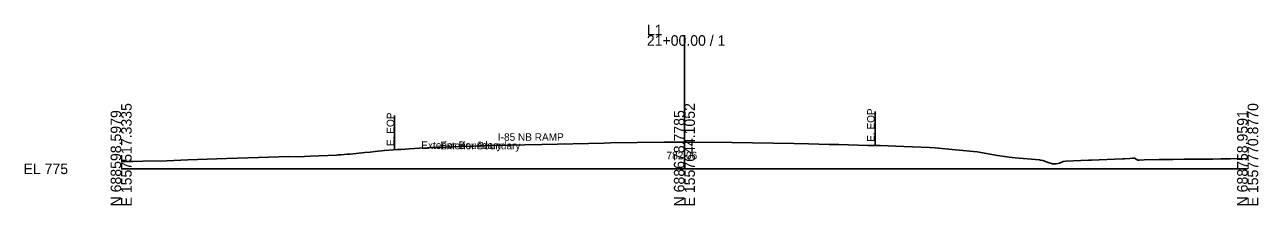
# Model space of a CAD drawing. Extents: x -26 to 2603, y -3010 to 9589.
# Drawn here: x -25.7 to 302.8, y 4490.3 to 4538.3 of the extents above; entities that cross this region are included whole.
import ezdxf

# ---------------------------------------------------------------- set-up
doc = ezdxf.new("R2010")
doc.units = 0
for name, color, linetype in [('Default', 7, 'Continuous'), ('Exist Cross Section Cell', 7, 'Continuous'), ('Exist XS Center Line Elevation Label', 7, 'Continuous'), ('Exist XS Ground Line', 7, 'Continuous'), ('Prop XS Label Text', 7, 'Continuous'), ('Prop XS Side Slope Text', 7, 'Continuous')]:
    doc.layers.add(name, color=color, linetype=linetype)

msp = doc.modelspace()

# ---------------------------------------------------------------- linework, layer by layer
at = {"layer": 'Exist Cross Section Cell'}
for p, q in [((150, 4500), (150, 4535.54)), ((0, 4500), (150, 4500)), ((150, 4500), (300, 4500))]:
    msp.add_line(p, q, dxfattribs=at)
at = {"layer": 'Exist XS Ground Line'}
msp.add_lwpolyline([(0, 4501.92), (3.11, 4502), (5.81, 4502.06), (12.15, 4502.16), (17.78, 4502.4), (28.04, 4502.77), (36.56, 4503.05), (44.62, 4503.25), (47.56, 4503.22), (48.85, 4503.28), (50.37, 4503.35), (57.37, 4503.68), (57.8, 4503.7), (58.21, 4503.72), (58.61, 4503.75), (59.42, 4503.81), (60.21, 4503.88), (61.01, 4503.95), (64.92, 4504.34), (66.32, 4504.47), (67.61, 4504.6), (70.17, 4504.84), (72.56, 4505.05), (73.59, 4505.13), (74.46, 4505.18), (76.79, 4505.33), (79.48, 4505.49), (81.47, 4505.58), (82.9, 4505.64), (85.1, 4505.72), (88.07, 4505.86), (90.52, 4505.96), (93.82, 4506.07), (96.75, 4506.16), (98.51, 4506.2), (112.02, 4506.51), (128.59, 4506.86), (130.32, 4506.9), (144.65, 4507.07), (145.29, 4507.07), (150, 4507.06), (162.63, 4507.02), (179.15, 4506.71), (183.09, 4506.63), (188.53, 4506.5), (191.15, 4506.44), (198.86, 4506.25), (200.22, 4506.25), (200.76, 4506.25), (201.33, 4506.23), (202.14, 4506.19), (208.43, 4505.93), (210.73, 4505.85), (215.24, 4505.71), (216.81, 4505.55), (222.2, 4505.06), (227.94, 4504.52), (233.41, 4503.59), (236.45, 4503.14), (237.29, 4502.99), (238.08, 4502.9), (244.52, 4502.37), (244.87, 4502.27), (245.44, 4502.26), (246.85, 4501.69), (248.07, 4501.3), (249.01, 4501.35), (249.91, 4501.53), (250.89, 4501.95), (251.6, 4502.03), (257.62, 4502.3), (258.42, 4502.3), (266.71, 4502.68), (267.16, 4502.69), (268.64, 4502.79), (269.34, 4502.82), (269.85, 4502.8), (270.75, 4502.31), (271.09, 4502.33), (272.43, 4502.42), (276.45, 4502.46), (277.48, 4502.47), (280.2, 4502.48), (283.12, 4502.57), (290.76, 4502.6), (292.88, 4502.65), (295.42, 4502.66), (300, 4502.71)], dxfattribs=at)
at = {"layer": 'Prop XS Label Text'}
for p, q in [((72.82, 4514.15), (72.82, 4505.15)), ((200.76, 4515.25), (200.76, 4506.25))]:
    msp.add_line(p, q, dxfattribs=at)

# ---------------------------------------------------------------- texts
at = {"layer": 'Default'}
for s, height, p in [('Exterior Boundary', 2, (79.92, 4505.29)), ('Exterior Boundary', 2, (84.92, 4505.19)), ('-', 0.0001, (0, 4500))]:
    msp.add_text(s, height=height, dxfattribs=at).set_placement(p)
at = {"layer": 'Exist Cross Section Cell'}
for s, p in [('L1', (140, 4535.54)), ('21+00.00 / 1', (140, 4532.74)), ('EL 775', (-26, 4498.6))]:
    msp.add_text(s, height=2.8, dxfattribs=at).set_placement(p)
for s, p in [('E 1557517.3335', (2.8, 4490)), ('E 1557770.8770', (302.8, 4490)), ('N 688598.5979', (0, 4490)), ('N 688678.7785', (150, 4490)), ('E 1557644.1052', (152.8, 4490)), ('N 688758.9591', (300, 4490))]:
    msp.add_text(s, height=2.8, rotation=90, dxfattribs=at).set_placement(p)
at = {"layer": 'Exist XS Center Line Elevation Label'}
msp.add_text('782.06', height=2, dxfattribs=at).set_placement((145.23, 4502.56))
at = {"layer": 'Prop XS Label Text'}
for p in [(72.72, 4506.07), (200.66, 4507.18)]:
    msp.add_text('E. EOP', height=2, rotation=90, dxfattribs=at).set_placement(p)
at = {"layer": 'Prop XS Side Slope Text'}
msp.add_text('I-85 NB RAMP', height=2, rotation=0.014, dxfattribs=at).set_placement((100.33, 4507.46))

doc.saveas('drawing.dxf')
